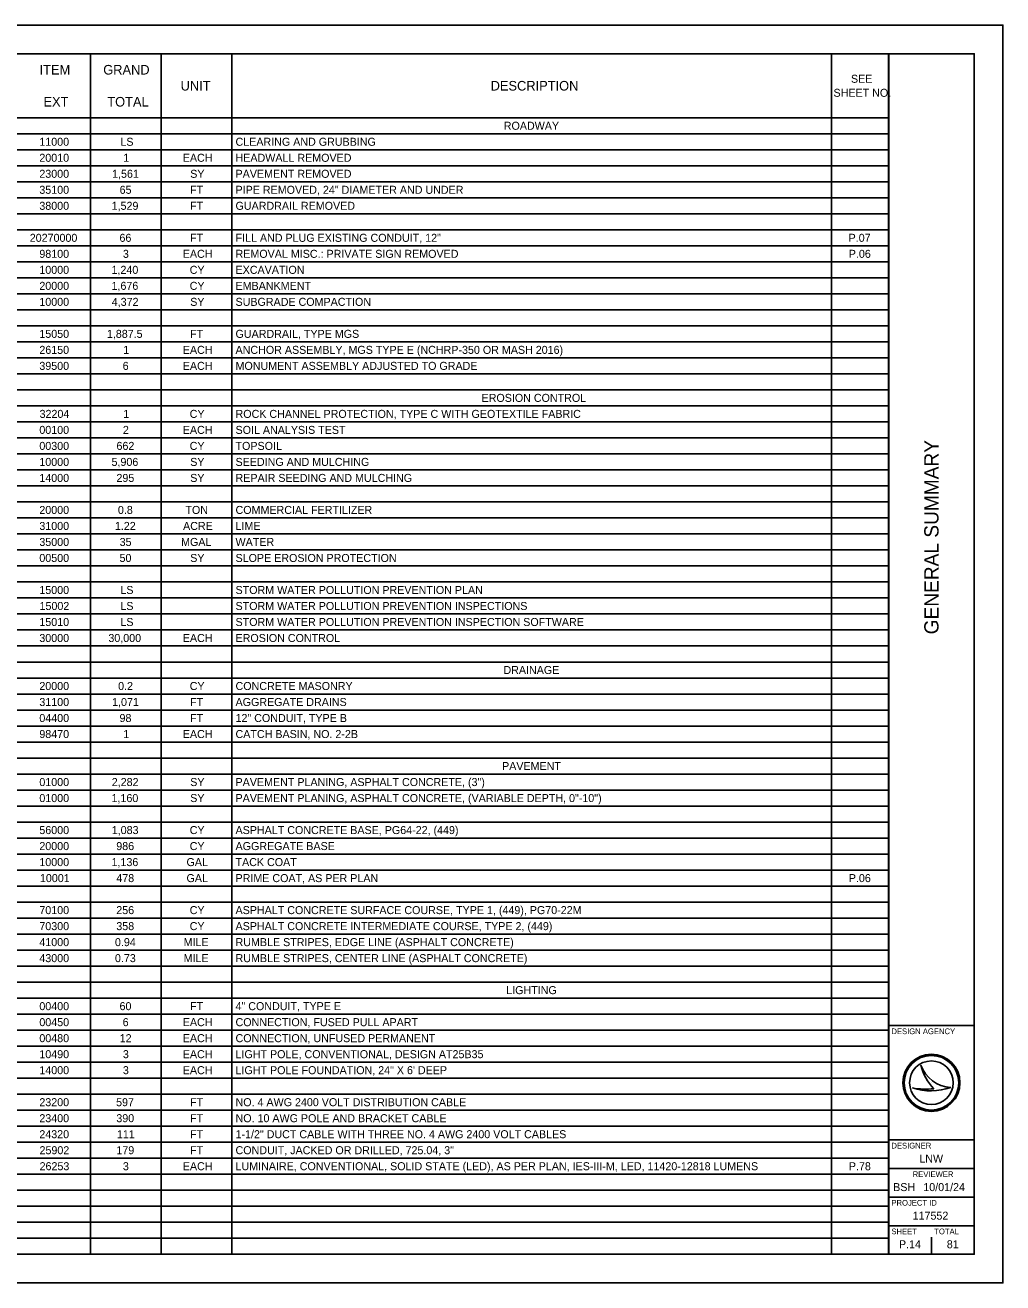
# Model space of a CAD drawing. Extents: x 0 to 34, y 0 to 22.
# Drawn here: x 16.89 to 34, y 0 to 22 of the extents above; entities that cross this region are included whole.
import ezdxf

# ---------------------------------------------------------------- set-up
doc = ezdxf.new("R2010")
doc.units = 0
for name, color, linetype in [('SH_Border', 7, 'Continuous'), ('SH_Cut_Line', 7, 'Continuous'), ('SH_Data', 7, 'Continuous'), ('SH_Text', 7, 'Continuous')]:
    doc.layers.add(name, color=color, linetype=linetype)

msp = doc.modelspace()

# ---------------------------------------------------------------- linework, layer by layer
at = {"layer": 'SH_Border'}
for p, q in [((32, 0.5), (32, 21.5)), ((32, 4.5), (33.5, 4.5)), ((32, 2.5), (33.5, 2.5)), ((32, 2), (33.5, 2)), ((32, 1.5), (33.5, 1.5)), ((32, 1), (33.5, 1))]:
    msp.add_line(p, q, dxfattribs=at)
msp.add_lwpolyline([(1.5, 21.5), (33.5, 21.5), (33.5, 0.5), (1.5, 0.5)], close=True, dxfattribs=at)
at = {"layer": 'SH_Cut_Line'}
msp.add_lwpolyline([(0, 0), (34, 0), (34, 22), (0, 22)], close=True, dxfattribs=at)
at = {"layer": 'SH_Data'}
for p, q in [((32.567, 3.81), (32.567, 3.81)), ((32.417, 3.41), (32.417, 3.41)), ((32.75, 3.5), (32.75, 3.5)), ((33.087, 3.419), (33.087, 3.419)), ((32.375, 0.675), (32.375, 0.675)), ((32.75, 0.5), (32.75, 0.8))]:
    msp.add_line(p, q, dxfattribs=at)
for radius in [0.5, 0.477, 0.477, 0.382]:
    msp.add_circle((32.75, 3.5), radius, dxfattribs=at)
for centre, radius, start, end in [((33.116, 3.998), 0.58, 198.9257, 198.9319), ((33.347, 3.97), 0.796, 191.6379, 191.6421), ((33.116, 3.998), 0.58, 198.9319, 267.1657), ((33.347, 3.97), 0.796, 191.6421, 226.0947), ((32.739, 4.37), 1.013, 251.4576, 290.0832), ((32.648, 4.654), 1.266, 259.4964, 259.4995), ((32.739, 4.37), 1.013, 251.4527, 251.4576), ((32.648, 4.654), 1.266, 259.4995, 276.6672)]:
    msp.add_arc(centre, radius, start, end, dxfattribs=at)
at = {"layer": 'SH_Text'}
for p, q in [((1.5, 21.5), (32.004, 21.5)), ((18.036, 21.5), (18.036, 0.5)), ((19.272, 21.5), (19.272, 0.5)), ((20.507, 21.5), (20.507, 0.5)), ((30.999, 21.5), (30.999, 0.5)), ((32.004, 21.5), (32.004, 0.5)), ((1.5, 20.38), (32.004, 20.38)), ((1.5, 20.1), (32.004, 20.1)), ((1.5, 19.82), (32.004, 19.82)), ((1.5, 19.54), (32.004, 19.54)), ((1.5, 19.26), (32.004, 19.26)), ((1.5, 18.98), (32.004, 18.98)), ((1.5, 18.7), (32.004, 18.7)), ((1.5, 18.42), (32.004, 18.42)), ((1.5, 18.14), (32.004, 18.14)), ((1.5, 17.86), (32.004, 17.86)), ((1.5, 17.58), (32.004, 17.58)), ((1.5, 17.3), (32.004, 17.3)), ((1.5, 17.02), (32.004, 17.02)), ((1.5, 16.74), (32.004, 16.74)), ((1.5, 16.46), (32.004, 16.46)), ((1.5, 16.18), (32.004, 16.18)), ((1.5, 15.9), (32.004, 15.9)), ((1.5, 15.62), (32.004, 15.62)), ((1.5, 15.34), (32.004, 15.34)), ((1.5, 15.06), (32.004, 15.06)), ((1.5, 14.78), (32.004, 14.78)), ((1.5, 14.5), (32.004, 14.5)), ((1.5, 14.22), (32.004, 14.22)), ((1.5, 13.94), (32.004, 13.94)), ((1.5, 13.66), (32.004, 13.66)), ((1.5, 13.38), (32.004, 13.38)), ((1.5, 13.1), (32.004, 13.1)), ((1.5, 12.82), (32.004, 12.82)), ((1.5, 12.54), (32.004, 12.54)), ((1.5, 12.26), (32.004, 12.26)), ((1.5, 11.98), (32.004, 11.98)), ((1.5, 11.7), (32.004, 11.7)), ((1.5, 11.42), (32.004, 11.42)), ((1.5, 11.14), (32.004, 11.14)), ((1.5, 10.86), (32.004, 10.86)), ((1.5, 10.58), (32.004, 10.58)), ((1.5, 10.3), (32.004, 10.3)), ((1.5, 10.02), (32.004, 10.02)), ((1.5, 9.74), (32.004, 9.74)), ((1.5, 9.46), (32.004, 9.46)), ((1.5, 9.18), (32.004, 9.18)), ((1.5, 8.9), (32.004, 8.9)), ((1.5, 8.62), (32.004, 8.62)), ((1.5, 8.34), (32.004, 8.34)), ((1.5, 8.06), (32.004, 8.06)), ((1.5, 7.78), (32.004, 7.78)), ((1.5, 7.5), (32.004, 7.5)), ((1.5, 7.22), (32.004, 7.22)), ((1.5, 6.94), (32.004, 6.94)), ((1.5, 6.66), (32.004, 6.66)), ((1.5, 6.38), (32.004, 6.38)), ((1.5, 6.1), (32.004, 6.1)), ((1.5, 5.82), (32.004, 5.82)), ((1.5, 5.54), (32.004, 5.54)), ((1.5, 5.26), (32.004, 5.26)), ((1.5, 4.98), (32.004, 4.98)), ((1.5, 4.7), (32.004, 4.7)), ((1.5, 4.42), (32.004, 4.42)), ((1.5, 4.14), (32.004, 4.14)), ((1.5, 3.86), (32.004, 3.86)), ((1.5, 3.58), (32.004, 3.58)), ((1.5, 3.3), (32.004, 3.3)), ((1.5, 3.02), (32.004, 3.02)), ((1.5, 2.74), (32.004, 2.74)), ((1.5, 2.46), (32.004, 2.46)), ((1.5, 2.18), (32.004, 2.18)), ((1.5, 1.9), (32.004, 1.9)), ((1.5, 1.62), (32.004, 1.62)), ((1.5, 1.34), (32.004, 1.34)), ((1.5, 1.06), (32.004, 1.06)), ((1.5, 0.78), (32.004, 0.78)), ((1.5, 0.5), (32.004, 0.5))]:
    msp.add_line(p, q, dxfattribs=at)

# ---------------------------------------------------------------- texts
at = {"layer": 'SH_Data'}
msp.add_text('GENERAL SUMMARY', height=0.25, rotation=90, dxfattribs=at).set_placement((32.875, 11.344))
for s, height, p in [('DESIGN AGENCY', 0.1, (32.05, 4.35)), ('DESIGNER', 0.1, (32.05, 2.35)), ('LNW', 0.14, (32.538, 2.105)), ('REVIEWER', 0.1, (32.422, 1.85)), ('BSH', 0.14, (32.08, 1.605)), ('10/01/24', 0.14, (32.608, 1.605)), ('PROJECT ID', 0.1, (32.05, 1.35)), ('117552', 0.14, (32.421, 1.105)), ('SHEET', 0.1, (32.05, 0.85)), ('TOTAL', 0.1, (32.8, 0.85)), ('P.14', 0.14, (32.182, 0.605)), ('81', 0.14, (33.019, 0.605))]:
    msp.add_text(s, height=height, dxfattribs=at).set_placement(p)
at = {"layer": 'SH_Text'}
for s, height, p in [('ITEM', 0.168, (17.144, 21.136)), ('GRAND', 0.168, (18.258, 21.136)), ('SEE ', 0.14, (31.342, 20.992)), ('UNIT', 0.168, (19.612, 20.856)), ('DESCRIPTION', 0.168, (25.037, 20.856)), ('EXT', 0.168, (17.212, 20.576)), ('TOTAL', 0.168, (18.329, 20.576)), ('SHEET NO.', 0.14, (31.037, 20.747)), ('ROADWAY', 0.14, (25.267, 20.17)), ('11000', 0.14, (17.14, 19.89)), ('LS', 0.14, (18.558, 19.89)), ('CLEARING AND GRUBBING', 0.14, (20.573, 19.89)), ('20010', 0.14, (17.14, 19.61)), ('1', 0.14, (18.608, 19.61)), ('EACH', 0.14, (19.65, 19.61)), ('HEADWALL REMOVED', 0.14, (20.573, 19.61)), ('23000', 0.14, (17.14, 19.33)), ('1,561', 0.14, (18.413, 19.33)), ('SY', 0.14, (19.78, 19.33)), ('PAVEMENT REMOVED', 0.14, (20.573, 19.33)), ('35100', 0.14, (17.14, 19.05)), ('65', 0.14, (18.545, 19.05)), ('FT', 0.14, (19.777, 19.05)), ('PIPE REMOVED, 24" DIAMETER AND UNDER', 0.14, (20.573, 19.05)), ('38000', 0.14, (17.14, 18.77)), ('1,529', 0.14, (18.405, 18.77)), ('FT', 0.14, (19.777, 18.77)), ('GUARDRAIL REMOVED', 0.14, (20.573, 18.77)), ('20270000', 0.14, (16.972, 18.21)), ('66', 0.14, (18.542, 18.21)), ('FT', 0.14, (19.777, 18.21)), ('FILL AND PLUG EXISTING CONDUIT, 12"', 0.14, (20.573, 18.21)), ('P.07', 0.14, (31.301, 18.21)), ('98100', 0.14, (17.14, 17.93)), ('3', 0.14, (18.602, 17.93)), ('EACH', 0.14, (19.65, 17.93)), ('REMOVAL MISC.: PRIVATE SIGN REMOVED', 0.14, (20.573, 17.93)), ('P.06', 0.14, (31.304, 17.93)), ('10000', 0.14, (17.14, 17.65)), ('1,240', 0.14, (18.403, 17.65)), ('CY', 0.14, (19.771, 17.65)), ('EXCAVATION', 0.14, (20.573, 17.65)), ('20000', 0.14, (17.14, 17.37)), ('1,676', 0.14, (18.403, 17.37)), ('CY', 0.14, (19.771, 17.37)), ('EMBANKMENT', 0.14, (20.573, 17.37)), ('10000', 0.14, (17.14, 17.09)), ('4,372', 0.14, (18.407, 17.09)), ('SY', 0.14, (19.78, 17.09)), ('SUBGRADE COMPACTION', 0.14, (20.573, 17.09)), ('15050', 0.14, (17.14, 16.53)), ('1,887.5', 0.14, (18.322, 16.53)), ('FT', 0.14, (19.777, 16.53)), ('GUARDRAIL, TYPE MGS', 0.14, (20.573, 16.53)), ('26150', 0.14, (17.14, 16.25)), ('1', 0.14, (18.608, 16.25)), ('EACH', 0.14, (19.65, 16.25)), ('ANCHOR ASSEMBLY, MGS TYPE E (NCHRP-350 OR MASH 2016)', 0.14, (20.573, 16.25)), ('39500', 0.14, (17.14, 15.97)), ('6', 0.14, (18.598, 15.97)), ('EACH', 0.14, (19.65, 15.97)), ('MONUMENT ASSEMBLY ADJUSTED TO GRADE', 0.14, (20.573, 15.97)), ('EROSION CONTROL', 0.14, (24.878, 15.41)), ('32204', 0.14, (17.144, 15.13)), ('1', 0.14, (18.608, 15.13)), ('CY', 0.14, (19.771, 15.13)), ('ROCK CHANNEL PROTECTION, TYPE C WITH GEOTEXTILE FABRIC', 0.14, (20.573, 15.13)), ('00100', 0.14, (17.14, 14.85)), ('2', 0.14, (18.602, 14.85)), ('EACH', 0.14, (19.65, 14.85)), ('SOIL ANALYSIS TEST', 0.14, (20.573, 14.85)), ('00300', 0.14, (17.14, 14.57)), ('662', 0.14, (18.49, 14.57)), ('CY', 0.14, (19.771, 14.57)), ('TOPSOIL', 0.14, (20.573, 14.57)), ('10000', 0.14, (17.14, 14.29)), ('5,906', 0.14, (18.403, 14.29)), ('SY', 0.14, (19.78, 14.29)), ('SEEDING AND MULCHING', 0.14, (20.573, 14.29)), ('14000', 0.14, (17.14, 14.01)), ('295', 0.14, (18.489, 14.01)), ('SY', 0.14, (19.78, 14.01)), ('REPAIR SEEDING AND MULCHING', 0.14, (20.573, 14.01)), ('20000', 0.14, (17.14, 13.45)), ('0.8', 0.14, (18.515, 13.45)), ('TON', 0.14, (19.696, 13.45)), ('COMMERCIAL FERTILIZER', 0.14, (20.573, 13.45)), ('31000', 0.14, (17.14, 13.17)), ('1.22', 0.14, (18.462, 13.17)), ('ACRE', 0.14, (19.655, 13.17)), ('LIME', 0.14, (20.573, 13.17)), ('35000', 0.14, (17.14, 12.89)), ('35', 0.14, (18.545, 12.89)), ('MGAL', 0.14, (19.62, 12.89)), ('WATER', 0.14, (20.573, 12.89)), ('00500', 0.14, (17.14, 12.61)), ('50', 0.14, (18.543, 12.61)), ('SY', 0.14, (19.78, 12.61)), ('SLOPE EROSION PROTECTION', 0.14, (20.573, 12.61)), ('15000', 0.14, (17.14, 12.05)), ('LS', 0.14, (18.558, 12.05)), ('STORM WATER POLLUTION PREVENTION PLAN', 0.14, (20.573, 12.05)), ('15002', 0.14, (17.143, 11.77)), ('LS', 0.14, (18.558, 11.77)), ('STORM WATER POLLUTION PREVENTION INSPECTIONS', 0.14, (20.573, 11.77)), ('15010', 0.14, (17.14, 11.49)), ('LS', 0.14, (18.558, 11.49)), ('STORM WATER POLLUTION PREVENTION INSPECTION SOFTWARE', 0.14, (20.573, 11.49)), ('30000', 0.14, (17.14, 11.21)), ('30,000', 0.14, (18.348, 11.21)), ('EACH', 0.14, (19.65, 11.21)), ('EROSION CONTROL', 0.14, (20.573, 11.21)), ('DRAINAGE', 0.14, (25.261, 10.65)), ('20000', 0.14, (17.14, 10.37)), ('0.2', 0.14, (18.518, 10.37)), ('CY', 0.14, (19.771, 10.37)), ('CONCRETE MASONRY', 0.14, (20.573, 10.37)), ('31100', 0.14, (17.14, 10.09)), ('1,071', 0.14, (18.413, 10.09)), ('FT', 0.14, (19.777, 10.09)), ('AGGREGATE DRAINS', 0.14, (20.573, 10.09)), ('04400', 0.14, (17.14, 9.81)), ('98', 0.14, (18.543, 9.81)), ('FT', 0.14, (19.777, 9.81)), ('12" CONDUIT, TYPE B', 0.14, (20.573, 9.81)), ('98470', 0.14, (17.14, 9.53)), ('1', 0.14, (18.608, 9.53)), ('EACH', 0.14, (19.65, 9.53)), ('CATCH BASIN, NO. 2-2B', 0.14, (20.573, 9.53)), ('PAVEMENT', 0.14, (25.237, 8.97)), ('01000', 0.14, (17.14, 8.69)), ('2,282', 0.14, (18.407, 8.69)), ('SY', 0.14, (19.78, 8.69)), ('PAVEMENT PLANING, ASPHALT CONCRETE, (3")', 0.14, (20.573, 8.69)), ('01000', 0.14, (17.14, 8.41)), ('1,160', 0.14, (18.403, 8.41)), ('SY', 0.14, (19.78, 8.41)), ('PAVEMENT PLANING, ASPHALT CONCRETE, (VARIABLE DEPTH, 0"-10")', 0.14, (20.573, 8.41)), ('56000', 0.14, (17.14, 7.85)), ('1,083', 0.14, (18.407, 7.85)), ('CY', 0.14, (19.771, 7.85)), ('ASPHALT CONCRETE BASE, PG64-22, (449)', 0.14, (20.573, 7.85)), ('20000', 0.14, (17.14, 7.57)), ('986', 0.14, (18.486, 7.57)), ('CY', 0.14, (19.771, 7.57)), ('AGGREGATE BASE', 0.14, (20.573, 7.57)), ('10000', 0.14, (17.14, 7.29)), ('1,136', 0.14, (18.403, 7.29)), ('GAL', 0.14, (19.715, 7.29)), ('TACK COAT', 0.14, (20.573, 7.29)), ('10001', 0.14, (17.15, 7.01)), ('478', 0.14, (18.487, 7.01)), ('GAL', 0.14, (19.715, 7.01)), ('PRIME COAT, AS PER PLAN', 0.14, (20.573, 7.01)), ('P.06', 0.14, (31.304, 7.01)), ('70100', 0.14, (17.14, 6.45)), ('256', 0.14, (18.486, 6.45)), ('CY', 0.14, (19.771, 6.45)), ('ASPHALT CONCRETE SURFACE COURSE, TYPE 1, (449), PG70-22M', 0.14, (20.573, 6.45)), ('70300', 0.14, (17.14, 6.17)), ('358', 0.14, (18.487, 6.17)), ('CY', 0.14, (19.771, 6.17)), ('ASPHALT CONCRETE INTERMEDIATE COURSE, TYPE 2, (449)', 0.14, (20.573, 6.17)), ('41000', 0.14, (17.14, 5.89)), ('0.94', 0.14, (18.463, 5.89)), ('MILE', 0.14, (19.665, 5.89)), ('RUMBLE STRIPES, EDGE LINE (ASPHALT CONCRETE)', 0.14, (20.573, 5.89)), ('43000', 0.14, (17.14, 5.61)), ('0.73', 0.14, (18.463, 5.61)), ('MILE', 0.14, (19.665, 5.61)), ('RUMBLE STRIPES, CENTER LINE (ASPHALT CONCRETE)', 0.14, (20.573, 5.61)), ('LIGHTING', 0.14, (25.31, 5.05)), ('00400', 0.14, (17.14, 4.77)), ('60', 0.14, (18.543, 4.77)), ('FT', 0.14, (19.777, 4.77)), ('4" CONDUIT, TYPE E', 0.14, (20.573, 4.77)), ('00450', 0.14, (17.14, 4.49)), ('6', 0.14, (18.598, 4.49)), ('EACH', 0.14, (19.65, 4.49)), ('CONNECTION, FUSED PULL APART', 0.14, (20.573, 4.49)), ('00480', 0.14, (17.14, 4.21)), ('12', 0.14, (18.546, 4.21)), ('EACH', 0.14, (19.65, 4.21)), ('CONNECTION, UNFUSED PERMANENT', 0.14, (20.573, 4.21)), ('10490', 0.14, (17.14, 3.93)), ('3', 0.14, (18.602, 3.93)), ('EACH', 0.14, (19.65, 3.93)), ('LIGHT POLE, CONVENTIONAL, DESIGN AT25B35', 0.14, (20.573, 3.93)), ('14000', 0.14, (17.14, 3.65)), ('3', 0.14, (18.602, 3.65)), ('EACH', 0.14, (19.65, 3.65)), ('LIGHT POLE FOUNDATION, 24" X 6\' DEEP', 0.14, (20.573, 3.65)), ('23200', 0.14, (17.14, 3.09)), ('597', 0.14, (18.483, 3.09)), ('FT', 0.14, (19.777, 3.09)), ('NO. 4 AWG 2400 VOLT DISTRIBUTION CABLE', 0.14, (20.573, 3.09)), ('23400', 0.14, (17.14, 2.81)), ('390', 0.14, (18.487, 2.81)), ('FT', 0.14, (19.777, 2.81)), ('NO. 10 AWG POLE AND BRACKET CABLE', 0.14, (20.573, 2.81)), ('24320', 0.14, (17.14, 2.53)), ('111', 0.14, (18.497, 2.53)), ('FT', 0.14, (19.777, 2.53)), ('1-1/2" DUCT CABLE WITH THREE NO. 4 AWG 2400 VOLT CABLES', 0.14, (20.573, 2.53)), ('25902', 0.14, (17.143, 2.25)), ('179', 0.14, (18.488, 2.25)), ('FT', 0.14, (19.777, 2.25)), ('CONDUIT, JACKED OR DRILLED, 725.04, 3"', 0.14, (20.573, 2.25)), ('26253', 0.14, (17.144, 1.97)), ('3', 0.14, (18.602, 1.97)), ('EACH', 0.14, (19.65, 1.97)), ('LUMINAIRE, CONVENTIONAL, SOLID STATE (LED), AS PER PLAN, IES-III-M, LED, 11420-12818 LUMENS', 0.14, (20.573, 1.97)), ('P.78', 0.14, (31.305, 1.97))]:
    msp.add_text(s, height=height, dxfattribs=at).set_placement(p)

doc.saveas('drawing.dxf')
